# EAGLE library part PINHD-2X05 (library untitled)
PIN HEADER
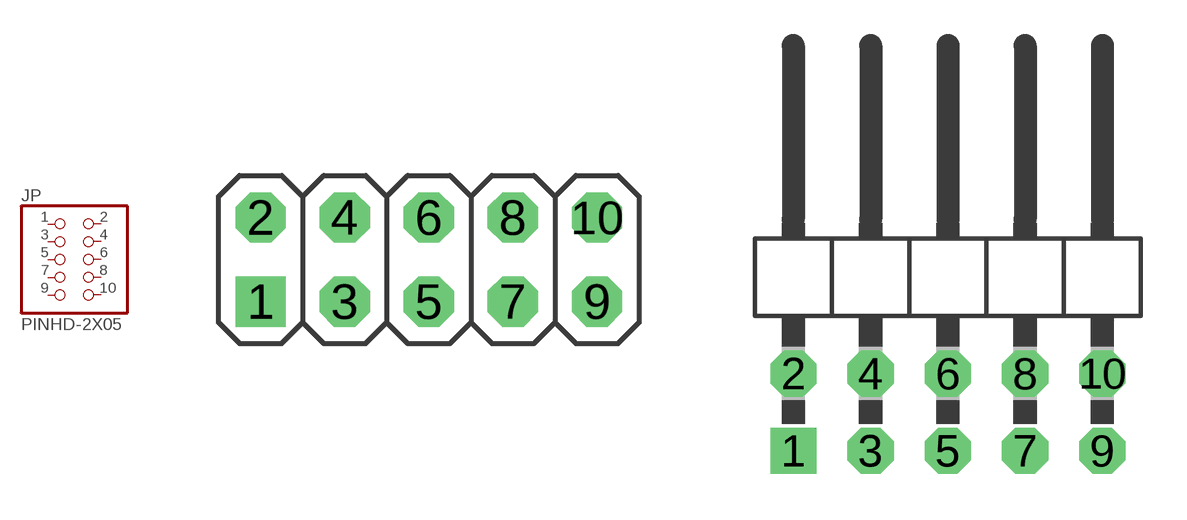
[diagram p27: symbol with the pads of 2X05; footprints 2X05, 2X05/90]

Designator prefix JP

## PINHD-2X05_2.54  [2X05]
1  1  pas
2  2  pas
3  3  pas
4  4  pas
5  5  pas
6  6  pas
7  7  pas
8  8  pas
9  9  pas
10  10  pas

## PINHD-2X05_2.54-90°  [2X05/90]
Pads as for 2X05

## PINHD-2X05_2.00  [2X05M]
Pads as for 2X05

## PINHD-2X05_2.54-SMD  [2X05SMD]
Pads as for 2X05

## PINHD-2X05_MICROMATCH  [MICROMATCH-10]
Pads as for 2X05

## PINHD-2X05_2.54-SMD-90°  [2X05SMD/90]
Pads as for 2X05

## Footprint 2X05 (pad centres in mm)
PIN HEADER - 2.54
drill 1.016 square: 1 -5.08,-1.27
drill 1.016 octagon: 2 -5.08,1.27; 3 -2.54,-1.27; 4 -2.54,1.27; 5 0,-1.27; 6 0,1.27; 7 2.54,-1.27; 8 2.54,1.27; 9 5.08,-1.27; 10 5.08,1.27

## Footprint 2X05/90 (pad centres in mm)
PIN HEADER - 2.54 90°
drill 1.016 square: 1 -5.08,-6.35
drill 1.016 octagon: 2 -5.08,-3.81; 3 -2.54,-6.35; 4 -2.54,-3.81; 5 0,-6.35; 6 0,-3.81; 7 2.54,-6.35; 8 2.54,-3.81; 9 5.08,-6.35; 10 5.08,-3.81

## Footprint 2X05M (pad centres in mm)
PIN HEADER - 2
drill 0.914 square: 1 -4,-1
drill 0.914 round: 2 -4,1; 3 -2,-1; 4 -2,1; 5 0,-1; 6 0,1; 7 2,-1; 8 2,1; 9 4,-1; 10 4,1

## Footprint 2X05SMD (pad centres in mm)
PIN HEADER - 2.54 SMD
smd 1.016 x 3.302: 1 -1.27,-3.81; 2 -1.27,1.27; 3 1.27,-3.81; 4 1.27,1.27; 5 3.81,-3.81; 6 3.81,1.27; 7 6.35,-3.81; 8 6.35,1.27; 9 8.89,-3.81; 10 8.89,1.27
